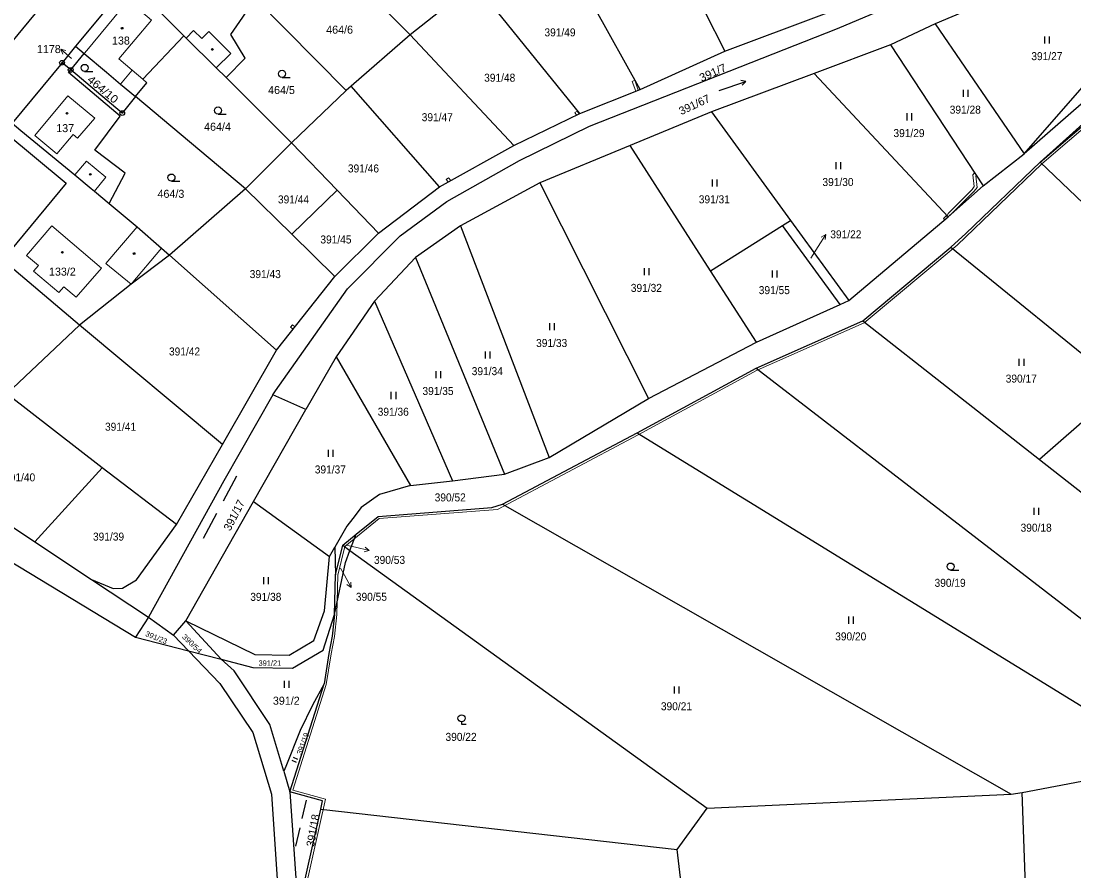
# Model space of a CAD drawing. Extents: x -758887 to -754328, y -1031688 to -1029144.
# Drawn here: x -756855.4 to -756631.8, y -1030649.6 to -1030469.1 of the extents above; entities that cross this region are included whole.
import ezdxf
from ezdxf.enums import TextEntityAlignment as Align

# ---------------------------------------------------------------- set-up
doc = ezdxf.new("R2010")
doc.units = 0
doc.header["$LTSCALE"] = 0.68
for name, color, linetype, lineweight in [('1', 7, 'Continuous', 25), ('13', 7, 'Continuous', 13), ('3', 7, 'Continuous', 25), ('4', 7, 'Continuous', 13), ('5', 7, 'Continuous', 25), ('7', 7, 'Continuous', 13), ('8', 7, 'Continuous', 25)]:
    doc.layers.add(name, color=color, linetype=linetype, lineweight=lineweight)
doc.layers.add('2', color=7, linetype='Continuous')

msp = doc.modelspace()

# ---------------------------------------------------------------- linework, layer by layer
at = {"layer": '1'}
for p, q in [((-756772.83, -1030472.01), (-756782.87, -1030461.9)), ((-756786.36, -1030483.83), (-756805.65, -1030464.28)), ((-756843.85, -1030474.46), (-756846.73, -1030477.94)), ((-756844.89, -1030479.47), (-756842.03, -1030475.98)), ((-756723.97, -1030483.63), (-756705.96, -1030475.51)), ((-756833.93, -1030488.63), (-756844.89, -1030479.47)), ((-756797.98, -1030494.94), (-756811.9, -1030481.12)), ((-756639, -1030499.08), (-756619.69, -1030482.51)), ((-756831.15, -1030485.11), (-756833.93, -1030488.63)), ((-756807.78, -1030504.72), (-756831.15, -1030485.11)), ((-756708.8, -1030488.36), (-756726.11, -1030495.54)), ((-756639, -1030499.08), (-756570.87, -1030564.48)), ((-756779.52, -1030514.17), (-756766.55, -1030504.28)), ((-756693.71, -1030512.52), (-756692.02, -1030511.46)), ((-756709, -1030522.14), (-756693.71, -1030512.52)), ((-756681.48, -1030529.29), (-756693.71, -1030512.52)), ((-756676.66, -1030532.79), (-756657.97, -1030517.15)), ((-756801.21, -1030538.97), (-756823.93, -1030518.8)), ((-756843, -1030533.68), (-756857.89, -1030521.09)), ((-756801.21, -1030538.97), (-756788.78, -1030523.35)), ((-756676.66, -1030532.79), (-756639.13, -1030562.23)), ((-756812.64, -1030559.04), (-756801.21, -1030538.97)), ((-756788.5, -1030540.45), (-756794.98, -1030551.59)), ((-756699.33, -1030542.79), (-756600.85, -1030618.83)), ((-756621.54, -1030546.75), (-756639.13, -1030562.23)), ((-756822.44, -1030576.02), (-756812.64, -1030559.04)), ((-756639.13, -1030562.23), (-756589.57, -1030601.12)), ((-756772.7, -1030567.77), (-756763.82, -1030566.76)), ((-756787.08, -1030580.42), (-756784.25, -1030578.12)), ((-756785.58, -1030581.54), (-756784.25, -1030578.12)), ((-756787.08, -1030580.42), (-756785.58, -1030581.54)), ((-756862.14, -1030581.18), (-756831.15, -1030599.97)), ((-756840.5, -1030587.68), (-756828.36, -1030595.75)), ((-756820.4, -1030596.5), (-756805.78, -1030603.66)), ((-756819.84, -1030602.89), (-756813.2, -1030609.79)), ((-756640.11, -1030704.83), (-756642.87, -1030632.93)), ((-756710.9, -1030688.54), (-756716.08, -1030645.06))]:
    msp.add_line(p, q, dxfattribs=at)
for points in [[(-757172.48, -1030761.99), (-757165.16, -1030751.81), (-757152.13, -1030736.25), (-757134.35, -1030719.37), (-757113.96, -1030707.3), (-757080.59, -1030692.2), (-757054.32, -1030678.02), (-757030.25, -1030661.2), (-756989.04, -1030625.89), (-756971.08, -1030607.26), (-756957.3, -1030592.11), (-756925.24, -1030554.85), (-756883.2, -1030504.8), (-756846.36, -1030460.12), (-756829.98, -1030442.25), (-756795.41, -1030407.31), (-756770.36, -1030384.93)], [(-756678.25, -1030434.07), (-756692.14, -1030442.68), (-756694.91, -1030437.03), (-756718.94, -1030449.91), (-756705.96, -1030475.51), (-756664.79, -1030459.98)], [(-756750.76, -1030495.5), (-756736.74, -1030488.74), (-756723.97, -1030483.63), (-756743.37, -1030448.74), (-756759.07, -1030461.12)], [(-756832.39, -1030460.6), (-756843.85, -1030474.46), (-756842.03, -1030475.98)], [(-756820.88, -1030472.21), (-756830.67, -1030462.33), (-756832.39, -1030460.6)], [(-756801.94, -1030548.46), (-756801.37, -1030547.66), (-756786.09, -1030526), (-756774.95, -1030514.69), (-756765.02, -1030507.42), (-756749.56, -1030498.73), (-756734.71, -1030491.44), (-756682.06, -1030470.67), (-756661.73, -1030462.01)], [(-756736.74, -1030488.74), (-756759.07, -1030461.12), (-756772.83, -1030472.01)], [(-756811.9, -1030481.12), (-756807.82, -1030477), (-756810.88, -1030471.97), (-756805.65, -1030464.28)], [(-756661.3, -1030469.71), (-756670.78, -1030474.13), (-756651.12, -1030504.1), (-756642.42, -1030497.3)], [(-756831.15, -1030485.11), (-756828.71, -1030482.2), (-756829.59, -1030481.46), (-756820.88, -1030472.21)], [(-756820.88, -1030472.21), (-756820.38, -1030472.7), (-756813.99, -1030479.04), (-756811.9, -1030481.12)], [(-756766.55, -1030504.28), (-756750.76, -1030495.5), (-756772.83, -1030472.01), (-756785.35, -1030482.95)], [(-756842.03, -1030475.98), (-756837.28, -1030479.96), (-756834.29, -1030482.47), (-756831.15, -1030485.11)], [(-756670.78, -1030474.13), (-756686.99, -1030480.2), (-756658.58, -1030510.71), (-756651.12, -1030504.1)], [(-756836.69, -1030507.85), (-756833.32, -1030501.38), (-756839.79, -1030496.51), (-756834.35, -1030489.33), (-756845.36, -1030480.04), (-756844.89, -1030479.47), (-756846.73, -1030477.94), (-756857.33, -1030490.77)], [(-756639, -1030499.08), (-756616.09, -1030478.48), (-756618.19, -1030476.22), (-756642.42, -1030497.3)], [(-756686.99, -1030480.2), (-756708.8, -1030488.36), (-756692.02, -1030511.46)], [(-756766.55, -1030504.28), (-756785.35, -1030482.95), (-756786.36, -1030483.83), (-756797.98, -1030494.94)], [(-756857.33, -1030490.77), (-756855.44, -1030492.33), (-756844, -1030501.79), (-756840.57, -1030504.63), (-756839.84, -1030505.24), (-756836.69, -1030507.85)], [(-756858.9, -1030492.67), (-756845.88, -1030503.51), (-756859.36, -1030519.85)], [(-756788.28, -1030505.05), (-756797.98, -1030494.94), (-756807.78, -1030504.72)], [(-756709, -1030522.14), (-756726.11, -1030495.54), (-756745.24, -1030503.49)], [(-756657.97, -1030517.15), (-756654.77, -1030514.2), (-756639, -1030499.08)], [(-756797.94, -1030514.37), (-756807.78, -1030504.72), (-756823.93, -1030518.8)], [(-756745.24, -1030503.49), (-756762.08, -1030512.56), (-756743.25, -1030561.83), (-756722.18, -1030549.28)], [(-756745.24, -1030503.49), (-756722.18, -1030549.28), (-756699.24, -1030537.31), (-756709, -1030522.14)], [(-756836.69, -1030507.85), (-756830.76, -1030512.77), (-756825.61, -1030517.32), (-756823.93, -1030518.8)], [(-756692.02, -1030511.46), (-756679.66, -1030528.47), (-756658.58, -1030510.71)], [(-756762.08, -1030512.56), (-756771.66, -1030519.32), (-756780.39, -1030528.61), (-756763.82, -1030566.76), (-756752.8, -1030565.34)], [(-756657.97, -1030517.15), (-756621.54, -1030546.75), (-756577.68, -1030582.38)], [(-756823.93, -1030518.8), (-756832.05, -1030524.99), (-756843, -1030533.68)], [(-756771.66, -1030519.32), (-756752.8, -1030565.34), (-756743.25, -1030561.83)], [(-756780.39, -1030528.61), (-756788.5, -1030540.45), (-756772.7, -1030567.77)], [(-756699.24, -1030537.31), (-756681.48, -1030529.29), (-756679.66, -1030528.47)], [(-756812.64, -1030559.04), (-756843, -1030533.68), (-756858.42, -1030548.27)], [(-756753.2, -1030571.72), (-756724.6, -1030556.59), (-756699.33, -1030542.79), (-756676.66, -1030532.79)], [(-756838.22, -1030563.97), (-756858.42, -1030548.27), (-756869.61, -1030559.21)], [(-756724.6, -1030556.59), (-756609.74, -1030627.21), (-756607.19, -1030628.79)], [(-756869.61, -1030559.21), (-756875.15, -1030564.63), (-756852.51, -1030579.69)], [(-756822.44, -1030576.02), (-756838.22, -1030563.97), (-756852.51, -1030579.69), (-756840.5, -1030587.68), (-756835.84, -1030589.6)], [(-756772.7, -1030567.77), (-756779.32, -1030569.66), (-756783.21, -1030572.43), (-756785, -1030574.73), (-756786.28, -1030576.37), (-756788.82, -1030580.84), (-756788.68, -1030586.69), (-756787.08, -1030580.42)], [(-756806.05, -1030571.15), (-756789.96, -1030582.86), (-756788.82, -1030580.84)], [(-756784.25, -1030578.12), (-756779.57, -1030574.3), (-756755.43, -1030572.44), (-756753.2, -1030571.72)], [(-756753.2, -1030571.72), (-756645.19, -1030633.3), (-756642.87, -1030632.93)], [(-756835.84, -1030589.6), (-756833.9, -1030589.57), (-756830.94, -1030587.79), (-756822.44, -1030576.02)], [(-756805.78, -1030603.66), (-756798.46, -1030603.77), (-756793.22, -1030600.65), (-756791.02, -1030594.36), (-756789.96, -1030582.86)], [(-756788.85, -1030595.13), (-756786.56, -1030584.08), (-756785.58, -1030581.54)], [(-756785.58, -1030581.54), (-756709.74, -1030636.25), (-756645.19, -1030633.3)], [(-756791.28, -1030602.69), (-756788.85, -1030595.13), (-756788.68, -1030586.69)], [(-756828.36, -1030595.75), (-756831.15, -1030599.97), (-756819.84, -1030602.89)], [(-756820.4, -1030596.5), (-756812.95, -1030604.67), (-756806.19, -1030606.42)], [(-756788.85, -1030595.13), (-756789.39, -1030599.75), (-756790.05, -1030603.42), (-756791.09, -1030609.89)], [(-756823.04, -1030599.57), (-756819.84, -1030602.89), (-756812.95, -1030604.67)], [(-756806.19, -1030606.42), (-756797.75, -1030606.53), (-756791.28, -1030602.69)], [(-756799.62, -1030628.45), (-756802.57, -1030618.5), (-756810.17, -1030607.13), (-756812.95, -1030604.67)], [(-756813.2, -1030609.79), (-756806.23, -1030620.22), (-756802.27, -1030633.34), (-756801.06, -1030651.39), (-756804.83, -1030673.68), (-756812.73, -1030693.17), (-756823.42, -1030732.5), (-756829.21, -1030744.27), (-756850.74, -1030770.98), (-756858.96, -1030776.84), (-756872.42, -1030782.82), (-756888.41, -1030786.68), (-756900.83, -1030788.9), (-756918.58, -1030789.61), (-756949.69, -1030787.03)], [(-756642.87, -1030632.93), (-756620.11, -1030628.61), (-756610.9, -1030629.71)], [(-756798.32, -1030632.84), (-756797.07, -1030651.12), (-756801.95, -1030674.56), (-756800.1, -1030668.48)], [(-756791.78, -1030636.51), (-756791.38, -1030634.72), (-756798.32, -1030632.84)], [(-756800.1, -1030668.48), (-756795.57, -1030653.56), (-756791.78, -1030636.51)], [(-756791.78, -1030636.51), (-756716.08, -1030645.06), (-756709.74, -1030636.25)]]:
    msp.add_lwpolyline(points, dxfattribs=at)
for points in [[(-756621.21, -1030473.01), (-756634.12, -1030459.75), (-756635.21, -1030458.62), (-756661.3, -1030469.71), (-756642.42, -1030497.3)], [(-756779.52, -1030514.17), (-756788.28, -1030505.05), (-756797.94, -1030514.37), (-756788.78, -1030523.35)], [(-756828.36, -1030595.75), (-756823.04, -1030599.57), (-756820.4, -1030596.5), (-756806.05, -1030571.15), (-756794.98, -1030551.59), (-756801.94, -1030548.46), (-756812.36, -1030566.75)], [(-756791.09, -1030609.89), (-756793.54, -1030614.43), (-756796.19, -1030619.78), (-756799.21, -1030627.41), (-756799.62, -1030628.45), (-756798.32, -1030632.84)]]:
    msp.add_lwpolyline(points, close=True, dxfattribs=at)
at = {"layer": '13'}
for points in [[(-756724.91, -1030484.01), (-756724.35, -1030483.78), (-756725.11, -1030481.67), (-756725.66, -1030481.92)], [(-756737.47, -1030489.09), (-756736.92, -1030488.83), (-756737.3, -1030488.24), (-756737.84, -1030488.51)], [(-756764.72, -1030503.26), (-756764.19, -1030502.97), (-756764.63, -1030502.42), (-756765.13, -1030502.76)], [(-756658.78, -1030510.49), (-756658.58, -1030510.71), (-756657.54, -1030509.78), (-756653.05, -1030505.25), (-756652.38, -1030504.43), (-756652.7, -1030501.94), (-756652.6, -1030501.84), (-756652.95, -1030501.32), (-756653.32, -1030501.76), (-756653, -1030504.25), (-756653.49, -1030504.85), (-756658.57, -1030509.97)], [(-756658.58, -1030510.71), (-756658.78, -1030510.49), (-756658.88, -1030510.61), (-756659, -1030510.49), (-756659.54, -1030511.02), (-756659.3, -1030511.32)], [(-756797.66, -1030534.51), (-756797.29, -1030534.04), (-756797.78, -1030533.64), (-756798.18, -1030534.09)]]:
    msp.add_lwpolyline(points, close=True, dxfattribs=at)
at = {"layer": '3'}
for p, q in [((-756638.001, -1030473.85), (-756638.001, -1030472.35)), ((-756637, -1030473.85), (-756637, -1030472.35)), ((-756841.923, -1030479.79), (-756840.173, -1030479.79)), ((-756800.013, -1030481.05), (-756798.263, -1030481.05)), ((-756701.504, -1030481.906), (-756702.265, -1030482.698)), ((-756655.321, -1030485.22), (-756655.321, -1030483.72)), ((-756654.32, -1030485.22), (-756654.32, -1030483.72)), ((-756813.603, -1030488.84), (-756811.853, -1030488.84)), ((-756667.281, -1030490.19), (-756667.281, -1030488.69)), ((-756666.28, -1030490.19), (-756666.28, -1030488.69)), ((-756682.361, -1030500.59), (-756682.361, -1030499.09)), ((-756681.36, -1030500.59), (-756681.36, -1030499.09)), ((-756708.621, -1030504.26), (-756708.621, -1030502.76)), ((-756707.62, -1030504.26), (-756707.62, -1030502.76)), ((-756823.493, -1030503.09), (-756821.743, -1030503.09)), ((-756723.051, -1030523.07), (-756723.051, -1030521.57)), ((-756722.05, -1030523.07), (-756722.05, -1030521.57)), ((-756695.881, -1030523.55), (-756695.881, -1030522.05)), ((-756694.88, -1030523.55), (-756694.88, -1030522.05)), ((-756743.161, -1030534.78), (-756743.161, -1030533.28)), ((-756742.16, -1030534.78), (-756742.16, -1030533.28)), ((-756756.831, -1030540.76), (-756756.831, -1030539.26)), ((-756755.83, -1030540.76), (-756755.83, -1030539.26)), ((-756643.441, -1030542.34), (-756643.441, -1030540.84)), ((-756642.44, -1030542.34), (-756642.44, -1030540.84)), ((-756767.301, -1030544.97), (-756767.301, -1030543.47)), ((-756766.3, -1030544.97), (-756766.3, -1030543.47)), ((-756776.801, -1030549.38), (-756776.801, -1030547.88)), ((-756775.8, -1030549.38), (-756775.8, -1030547.88)), ((-756790.161, -1030561.64), (-756790.161, -1030560.14)), ((-756789.16, -1030561.64), (-756789.16, -1030560.14)), ((-756812.431, -1030571.006), (-756809.614, -1030565.708)), ((-756816.656, -1030578.953), (-756813.839, -1030573.655)), ((-756640.271, -1030574.01), (-756640.271, -1030572.51)), ((-756639.27, -1030574.01), (-756639.27, -1030572.51)), ((-756803.851, -1030588.7), (-756803.851, -1030587.2)), ((-756802.85, -1030588.7), (-756802.85, -1030587.2)), ((-756658.033, -1030585.72), (-756656.283, -1030585.72)), ((-756679.651, -1030597.1), (-756679.651, -1030595.6)), ((-756678.65, -1030597.1), (-756678.65, -1030595.6)), ((-756799.511, -1030610.76), (-756799.511, -1030609.26)), ((-756798.51, -1030610.76), (-756798.51, -1030609.26)), ((-756716.661, -1030611.94), (-756716.661, -1030610.44)), ((-756715.66, -1030611.94), (-756715.66, -1030610.44)), ((-756796.651, -1030625.982), (-756797.562, -1030625.558)), ((-756796.935, -1030626.59), (-756797.845, -1030626.165)), ((-756795.732, -1030638.514), (-756794.828, -1030634.597)), ((-756797.089, -1030644.389), (-756796.184, -1030640.472))]:
    msp.add_line(p, q, dxfattribs=at)
for points in [[(-756707.178, -1030483.859), (-756701.504, -1030481.906), (-756702.592, -1030481.75)], [(-756761.89, -1030617.942), (-756761.89, -1030618.44), (-756760.889, -1030618.44)]]:
    msp.add_lwpolyline(points, dxfattribs=at)
for centre in [(-756841.9229, -1030479.0398), (-756800.0129, -1030480.2998), (-756813.6029, -1030488.0898), (-756823.4929, -1030502.3398), (-756658.0329, -1030584.9698), (-756761.8893, -1030617.1909)]:
    msp.add_circle(centre, 0.75, dxfattribs=at)
at = {"layer": '4'}
for p, q in [((-756818.79, -1030471.11), (-756820.38, -1030472.7)), ((-756817.06, -1030472.83), (-756818.79, -1030471.11)), ((-756815.54, -1030471.31), (-756817.06, -1030472.83)), ((-756815.54, -1030471.31), (-756810.86, -1030475.96)), ((-756813.99, -1030479.04), (-756810.86, -1030475.96)), ((-756831.85, -1030479.56), (-756834.29, -1030482.47)), ((-756829.59, -1030481.46), (-756831.85, -1030479.56)), ((-756852.53, -1030493.43), (-756845.51, -1030484.96)), ((-756839.77, -1030489.71), (-756845.51, -1030484.96)), ((-756638.66, -1030499.45), (-756619.73, -1030483.2)), ((-756843.42, -1030493.96), (-756839.77, -1030489.71)), ((-756847.83, -1030497.32), (-756852.53, -1030493.43)), ((-756844.39, -1030493.16), (-756847.83, -1030497.32)), ((-756843.42, -1030493.96), (-756844.39, -1030493.16)), ((-756841.54, -1030498.83), (-756844, -1030501.79)), ((-756837.39, -1030502.27), (-756841.54, -1030498.83)), ((-756839.84, -1030505.24), (-756837.39, -1030502.27)), ((-756754.27, -1030572.85), (-756724.35, -1030557.02)), ((-756786.64, -1030580.7), (-756788.18, -1030586.76)), ((-756788.18, -1030586.76), (-756788.35, -1030595.17)), ((-756790.6, -1030610), (-756789.55, -1030603.48)), ((-756797.69, -1030632.49), (-756790.6, -1030610)), ((-756797.69, -1030632.49), (-756790.79, -1030634.36)), ((-756790.79, -1030634.36), (-756795.08, -1030653.68))]:
    msp.add_line(p, q, dxfattribs=at)
for points in [[(-756831.85, -1030479.56), (-756834.67, -1030477.12), (-756827.74, -1030468.94), (-756832.68, -1030464.75), (-756830.67, -1030462.33)], [(-756842.03, -1030475.98), (-756841.48, -1030475.32), (-756832.68, -1030464.75)], [(-756724.35, -1030557.02), (-756699.1, -1030543.23), (-756676.39, -1030533.22), (-756656.66, -1030516.71), (-756638.66, -1030499.45)], [(-756830.76, -1030512.77), (-756837.42, -1030520.56), (-756832.05, -1030524.99), (-756825.61, -1030517.32)], [(-756786.64, -1030580.7), (-756779.38, -1030574.79), (-756754.27, -1030572.85)], [(-756788.35, -1030595.17), (-756788.89, -1030599.81), (-756789.55, -1030603.48)]]:
    msp.add_lwpolyline(points, dxfattribs=at)
msp.add_lwpolyline([(-756854.27, -1030518.87), (-756848.89, -1030512.62), (-756838.36, -1030521.55), (-756843.71, -1030527.76), (-756846.35, -1030525.53), (-756847.39, -1030526.75), (-756852.76, -1030522.25), (-756851.71, -1030521.02)], close=True, dxfattribs=at)
at = {"layer": '5'}
for centre in [(-756833.9568, -1030470.6192), (-756814.7968, -1030475.1292), (-756845.6668, -1030488.6892), (-756840.7268, -1030501.6592), (-756846.6568, -1030518.2192), (-756831.4168, -1030518.4792)]:
    msp.add_circle(centre, 0.175, dxfattribs=at)
at = {"layer": '7'}
for p, q in [((-756847.005, -1030475.061), (-756846.578, -1030476.096)), ((-756684.56, -1030514.405), (-756685.515, -1030514.989)), ((-756781.476, -1030581.555), (-756782.339, -1030580.842)), ((-756785.315, -1030589.395), (-756785.363, -1030588.276))]:
    msp.add_line(p, q, dxfattribs=at)
for points in [[(-756844.74, -1030477.03), (-756847.005, -1030475.061), (-756845.921, -1030475.34)], [(-756687.68, -1030519.43), (-756686.15, -1030516.95), (-756684.56, -1030514.405), (-756684.666, -1030515.52)], [(-756786.1, -1030580.47), (-756784.4, -1030580.88), (-756781.476, -1030581.555), (-756782.564, -1030581.818)], [(-756787.57, -1030585.3), (-756786.77, -1030586.77), (-756785.315, -1030589.395), (-756786.239, -1030588.762)]]:
    msp.add_lwpolyline(points, dxfattribs=at)
at = {"layer": '8'}
for centre, radius in [((-756846.73, -1030477.9399), 0.5), ((-756846.73, -1030477.9399), 0.0303), ((-756844.89, -1030479.4699), 0.5), ((-756844.89, -1030479.4699), 0.0303), ((-756833.93, -1030488.6299), 0.5), ((-756833.93, -1030488.6299), 0.0303)]:
    msp.add_circle(centre, radius, dxfattribs=at)

# ---------------------------------------------------------------- texts
at = {"layer": '2'}
for s, p in [('464/6', (-756787.78, -1030471.77)), ('138', (-756834.219, -1030474.09)), ('464/5', (-756800.12, -1030484.6)), ('137', (-756846.059, -1030492.69)), ('464/4', (-756813.71, -1030492.39)), ('464/3', (-756823.6, -1030506.64)), ('133/2', (-756846.65, -1030523.17)), ('391/2', (-756799.1, -1030614.31))]:
    msp.add_text(s, height=1.7, dxfattribs=at).set_placement(p, align=Align.CENTER)
at = {"layer": '2', "width": 0.95}
for s, height, p in [('391/49', 1.7, (-756740.979, -1030472.35)), ('391/27', 1.7, (-756637.589, -1030477.4)), ('391/48', 1.7, (-756753.779, -1030481.98)), ('391/28', 1.7, (-756654.919, -1030488.77)), ('391/47', 1.7, (-756767.039, -1030490.37)), ('391/29', 1.7, (-756666.869, -1030493.74)), ('391/46', 1.7, (-756782.719, -1030501.25)), ('391/30', 1.7, (-756681.949, -1030504.14)), ('391/44', 1.7, (-756797.569, -1030507.83)), ('391/31', 1.7, (-756708.209, -1030507.81)), ('391/45', 1.7, (-756788.559, -1030516.34)), ('391/43', 1.7, (-756803.569, -1030523.69)), ('391/32', 1.7, (-756722.639, -1030526.62)), ('391/55', 1.7, (-756695.469, -1030527.1)), ('391/42', 1.7, (-756820.709, -1030540.13)), ('391/33', 1.7, (-756742.749, -1030538.33)), ('391/34', 1.7, (-756756.419, -1030544.31)), ('390/17', 1.7, (-756643.029, -1030545.89)), ('391/35', 1.7, (-756766.889, -1030548.52)), ('391/36', 1.7, (-756776.389, -1030552.93)), ('391/41', 1.7, (-756834.299, -1030556.11)), ('391/40', 1.7, (-756855.719, -1030566.87)), ('391/37', 1.7, (-756789.749, -1030565.19)), ('390/52', 1.7, (-756764.289, -1030571.13)), ('390/18', 1.7, (-756639.869, -1030577.56)), ('391/39', 1.7, (-756836.849, -1030579.45)), ('390/19', 1.7, (-756658.139, -1030589.27)), ('391/38', 1.7, (-756803.449, -1030592.25)), ('390/20', 1.7, (-756679.239, -1030600.65)), ('391/21', 1.14, (-756802.589, -1030606.04)), ('390/21', 1.7, (-756716.249, -1030615.49)), ('390/22', 1.7, (-756761.989, -1030621.99))]:
    msp.add_text(s, height=height, dxfattribs=at).set_placement(p, align=Align.CENTER)
at = {"layer": '2'}
msp.add_text('1178', height=1.7, dxfattribs=at).set_placement((-756847, -1030475.9), align=Align.RIGHT)
for s, height, rotation, width, p in [('391/7', 1.7, 24, 1.05, (-756708.1932, -1030480.8235)), ('464/10', 1.7, 320, 1.1, (-756838.5914, -1030484.2566)), ('390/54', 1.14, 316, 1.1, (-756819.501, -1030601.7853))]:
    msp.add_text(s, height=height, rotation=rotation, dxfattribs=dict(at, width=width)).set_placement(p, align=Align.CENTER)
for s, height, rotation, p in [('391/67', 1.7, 25, (-756712.0807, -1030487.6284)), ('391/17', 1.7, 63, (-756809.4212, -1030574.4484)), ('391/23', 1.14, 338, (-756826.9, -1030600.576)), ('391/19', 1.14, 70, (-756795.0465, -1030622.775)), ('391/18', 1.7, 80, (-756792.6046, -1030641.1691))]:
    msp.add_text(s, height=height, rotation=rotation, dxfattribs=at).set_placement(p, align=Align.CENTER)
at = {"layer": '2', "width": 0.95}
for s, p in [('391/22', (-756683.58, -1030515.25)), ('390/53', (-756780.48, -1030584.403)), ('390/55', (-756784.33, -1030592.233))]:
    msp.add_text(s, height=1.7, dxfattribs=at).set_placement(p)

doc.saveas('drawing.dxf')
